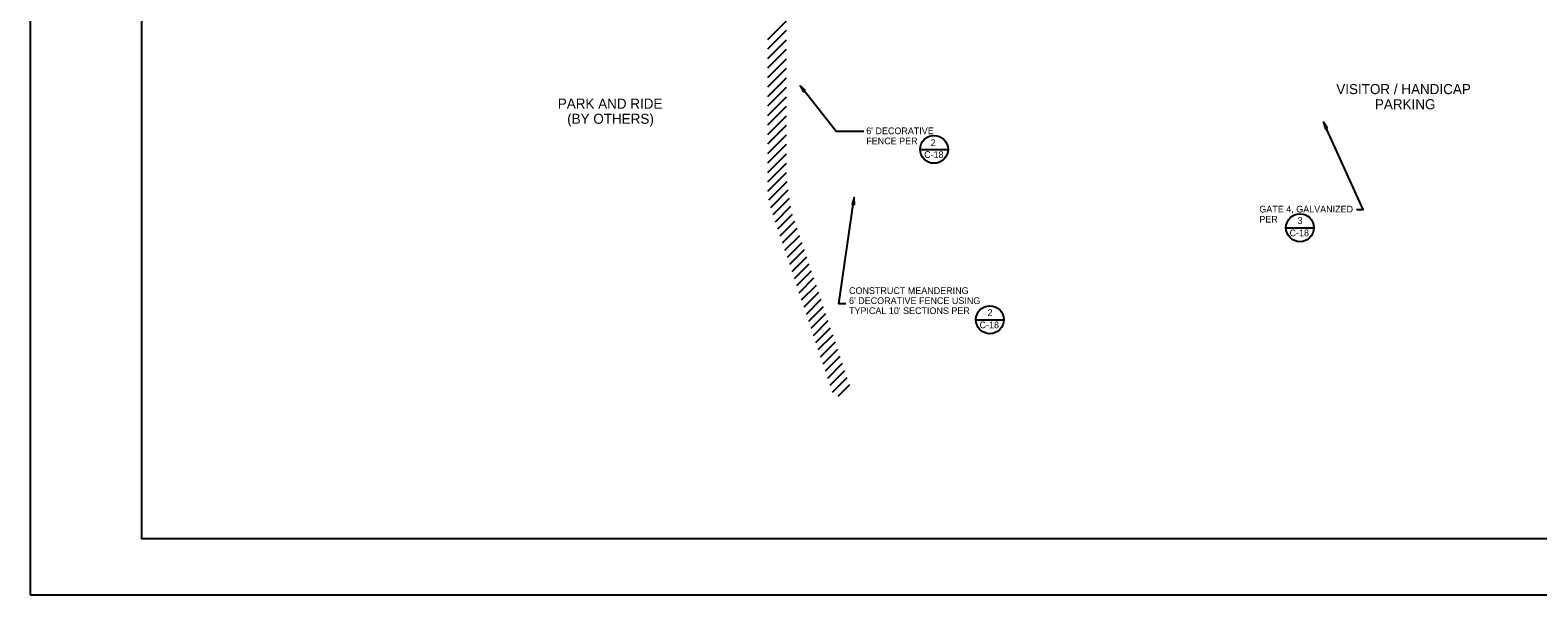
# Model space of a CAD drawing. Extents: x 0 to 3.5, y 0 to 2.5.
# Drawn here: x 0 to 2.248, y 0 to 0.842 of the extents above; entities that cross this region are included whole.
import ezdxf

# ---------------------------------------------------------------- set-up
doc = ezdxf.new("R2010")
doc.units = 0
for name, color, linetype in [('C-MARK', 7, 'Continuous'), ('C-TEXT', 7, 'Continuous'), ('C-TEXT-TITL', 7, 'Continuous'), ('G-TTLB-OTLN', 7, 'Continuous'), ('G-TTLB-VIEW', 7, 'Continuous'), ('Pavement Hatch', 7, 'Continuous')]:
    doc.layers.add(name, color=color, linetype=linetype)

msp = doc.modelspace()

# ---------------------------------------------------------------- linework, layer by layer
at = {"layer": 'C-MARK'}
for p, q in [((1.327, 0.6639), (1.3687, 0.6639)), ((1.8726, 0.547), (1.9143, 0.547)), ((1.4103, 0.4099), (1.452, 0.4099))]:
    msp.add_line(p, q, dxfattribs=at)
for points in [[(1.2431, 0.6906), (1.2018, 0.6906), (1.1547, 0.7506)], [(1.9777, 0.5744), (1.9877, 0.5744), (1.9288, 0.7043)], [(1.2161, 0.4337), (1.2061, 0.4337), (1.2274, 0.5817)]]:
    msp.add_lwpolyline(points, dxfattribs=at)
for centre in [(1.3479, 0.6639), (1.8935, 0.547), (1.4311, 0.4099)]:
    msp.add_circle(centre, 0.0208, dxfattribs=at)
at = {"layer": 'C-TEXT'}
for points in [[(1.1562, 0.7517), (1.1484, 0.7588), (1.1533, 0.7495)], [(1.9348, 0.6956), (1.9288, 0.7043), (1.9315, 0.6941)], [(1.2293, 0.5814), (1.2289, 0.592), (1.2256, 0.582)]]:
    msp.add_lwpolyline(points, close=True, dxfattribs=at)
at = {"layer": 'G-TTLB-OTLN'}
msp.add_lwpolyline([(0, 0), (3.5, 0), (3.5, 2.5), (0, 2.5)], close=True, dxfattribs=at)
at = {"layer": 'G-TTLB-VIEW'}
msp.add_lwpolyline([(0.1667, 2.4167), (3.0729, 2.4167), (3.0729, 0.0833), (0.1667, 0.0833)], close=True, dxfattribs=at)
at = {"layer": 'Pavement Hatch'}
for p, q in [((1.1, 0.8277), (1.1278, 0.8554)), ((1.1, 0.8135), (1.1278, 0.8413)), ((1.1, 0.7994), (1.1278, 0.8271)), ((1.1, 0.7852), (1.1278, 0.813)), ((1.1, 0.7711), (1.1278, 0.7988)), ((1.1, 0.7569), (1.1278, 0.7847)), ((1.1, 0.7428), (1.1278, 0.7705)), ((1.1, 0.7286), (1.1278, 0.7564)), ((1.1, 0.7145), (1.1278, 0.7423)), ((1.1, 0.7004), (1.1278, 0.7281)), ((1.1, 0.6862), (1.1278, 0.714)), ((1.1, 0.6721), (1.1278, 0.6998)), ((1.1, 0.6579), (1.1278, 0.6857)), ((1.1, 0.6438), (1.1278, 0.6716)), ((1.1, 0.6296), (1.1278, 0.6574)), ((1.1, 0.6155), (1.1278, 0.6433)), ((1.1001, 0.6015), (1.1281, 0.6294)), ((1.1015, 0.5887), (1.1288, 0.616)), ((1.1043, 0.5773), (1.1304, 0.6035)), ((1.1078, 0.5667), (1.1323, 0.5912)), ((1.1114, 0.5561), (1.1342, 0.579)), ((1.1149, 0.5456), (1.1369, 0.5675)), ((1.1185, 0.535), (1.1404, 0.5569)), ((1.122, 0.5244), (1.144, 0.5463)), ((1.1256, 0.5138), (1.1475, 0.5357)), ((1.1291, 0.5032), (1.1511, 0.5251)), ((1.1327, 0.4926), (1.1546, 0.5145)), ((1.1362, 0.482), (1.1582, 0.5039)), ((1.1398, 0.4714), (1.1617, 0.4933)), ((1.1433, 0.4608), (1.1653, 0.4828)), ((1.1469, 0.4502), (1.1688, 0.4722)), ((1.1504, 0.4396), (1.1724, 0.4616)), ((1.154, 0.429), (1.1759, 0.451)), ((1.1575, 0.4184), (1.1795, 0.4404)), ((1.1611, 0.4079), (1.183, 0.4298)), ((1.1646, 0.3973), (1.1866, 0.4192)), ((1.1682, 0.3867), (1.1901, 0.4086)), ((1.1717, 0.3761), (1.1937, 0.398)), ((1.1753, 0.3655), (1.1972, 0.3874)), ((1.1788, 0.3549), (1.2008, 0.3768)), ((1.1824, 0.3443), (1.2043, 0.3662)), ((1.1859, 0.3337), (1.2079, 0.3557)), ((1.1895, 0.3231), (1.2114, 0.3451)), ((1.193, 0.3125), (1.215, 0.3345)), ((1.1966, 0.3019), (1.2185, 0.3239)), ((1.2049, 0.2961), (1.2221, 0.3133))]:
    msp.add_line(p, q, dxfattribs=at)

# ---------------------------------------------------------------- texts
at = {"layer": 'C-TEXT'}
for s, p in [("6' DECORATIVE", (1.2468, 0.6865)), ('FENCE PER', (1.2468, 0.6715)), ('2', (1.3428, 0.6687)), ('C-18', (1.3331, 0.6511)), ('GATE 4, GALVANIZED', (1.833, 0.5698)), ('PER', (1.833, 0.5548)), ('3', (1.8899, 0.5527)), ('C-18', (1.878, 0.5344)), ('CONSTRUCT MEANDERING', (1.2211, 0.4484)), ("TYPICAL 10' SECTIONS PER", (1.2211, 0.4184)), ("6' DECORATIVE FENCE USING ", (1.2211, 0.4334)), ('C-18', (1.4157, 0.3973)), ('2', (1.4276, 0.4156))]:
    msp.add_text(s, height=0.01, dxfattribs=at).set_placement(p)
at = {"layer": 'C-TEXT-TITL'}
for s, p in [('VISITOR / HANDICAP', (1.9477, 0.7462)), ('PARK AND RIDE', (0.7868, 0.7245)), ('PARKING', (2.0053, 0.7237)), ('(BY OTHERS)', (0.8008, 0.702))]:
    msp.add_text(s, height=0.015, dxfattribs=at).set_placement(p)

doc.saveas('drawing.dxf')
